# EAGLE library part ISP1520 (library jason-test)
4-port USB hub
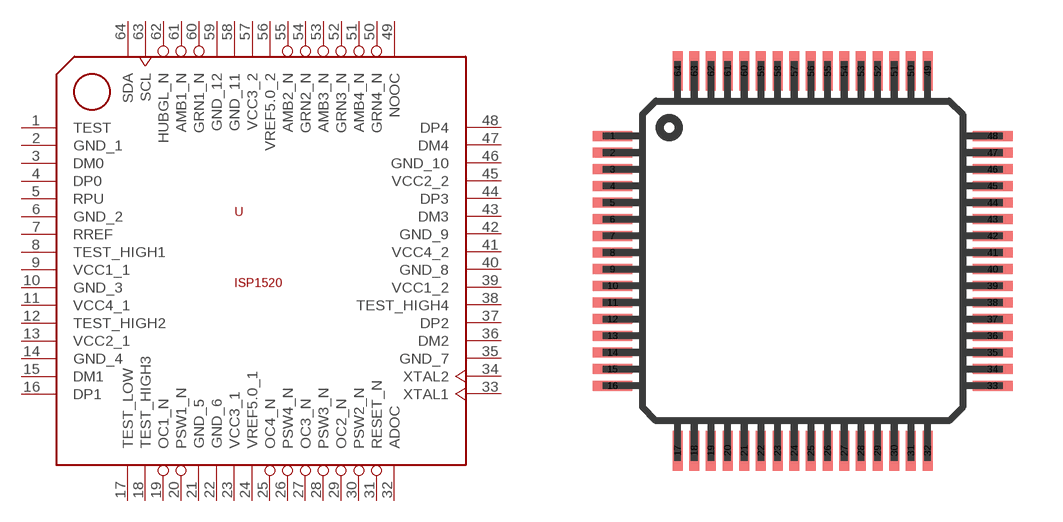
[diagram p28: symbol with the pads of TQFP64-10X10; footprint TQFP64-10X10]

Designator prefix -

## ISP1520  [TQFP64-10X10]
1  TEST
2  GND_1  pwr
3  DM0
4  DP0
5  RPU  in
6  GND_2  pwr
7  RREF  in
8  TEST_HIGH1
9  VCC1_1  pwr
10  GND_3  pwr
11  VCC4_1  pwr
12  TEST_HIGH2
13  VCC2_1  pwr
14  GND_4  pwr
15  DM1
16  DP1
17  TEST_LOW
18  TEST_HIGH3
19  OC1_N
20  PSW1_N
21  GND_5  pwr
22  GND_6  pwr
23  VCC3_1  pwr
24  VREF5.0_1  pwr
25  OC4_N
26  PSW4_N
27  OC3_N
28  PSW3_N
29  OC2_N
30  PSW2_N
31  RESET_N  in
32  ADOC  in
33  XTAL1  in
34  XTAL2
35  GND_7  pwr
36  DM2
37  DP2
38  TEST_HIGH4
39  VCC1_2  pwr
40  GND_8  pwr
41  VCC4_2  pwr
42  GND_9  pwr
43  DM3
44  DP3
45  VCC2_2  pwr
46  GND_10  pwr
47  DM4
48  DP4
49  NOOC  in
50  GRN4_N
51  AMB4_N
52  GRN3_N
53  AMB3_N
54  GRN2_N
55  AMB2_N
56  VREF5.0_2  pwr
57  VCC3_2  pwr
58  GND_11  pwr
59  GND_12  pwr
60  GRN1_N
61  AMB1_N
62  HUBGL_N  out
63  SCL
64  SDA

## Footprint TQFP64-10X10 (pad centres in mm)
Thin Quad Flat Pack package type TQ
smd 1.2 x 0.3: 1 -5.7,3.75; 2 -5.7,3.25; 3 -5.7,2.75; 4 -5.7,2.25; 5 -5.7,1.75; 6 -5.7,1.25; 7 -5.7,0.75; 8 -5.7,0.25; 9 -5.7,-0.25; 10 -5.7,-0.75; 11 -5.7,-1.25; 12 -5.7,-1.75; 13 -5.7,-2.25; 14 -5.7,-2.75; 15 -5.7,-3.25; 16 -5.7,-3.75; 33 5.7,-3.75; 34 5.7,-3.25; 35 5.7,-2.75; 36 5.7,-2.25; 37 5.7,-1.75; 38 5.7,-1.25; 39 5.7,-0.75; 40 5.7,-0.25; 41 5.7,0.25; 42 5.7,0.75; 43 5.7,1.25; 44 5.7,1.75; 45 5.7,2.25; 46 5.7,2.75; 47 5.7,3.25; 48 5.7,3.75
smd 0.3 x 1.2: 17 -3.75,-5.7; 18 -3.25,-5.7; 19 -2.75,-5.7; 20 -2.25,-5.7; 21 -1.75,-5.7; 22 -1.25,-5.7; 23 -0.75,-5.7; 24 -0.25,-5.7; 25 0.25,-5.7; 26 0.75,-5.7; 27 1.25,-5.7; 28 1.75,-5.7; 29 2.25,-5.7; 30 2.75,-5.7; 31 3.25,-5.7; 32 3.75,-5.7; 49 3.75,5.7; 50 3.25,5.7; 51 2.75,5.7; 52 2.25,5.7; 53 1.75,5.7; 54 1.25,5.7; 55 0.75,5.7; 56 0.25,5.7; 57 -0.25,5.7; 58 -0.75,5.7; 59 -1.25,5.7; 60 -1.75,5.7; 61 -2.25,5.7; 62 -2.75,5.7; 63 -3.25,5.7; 64 -3.75,5.7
